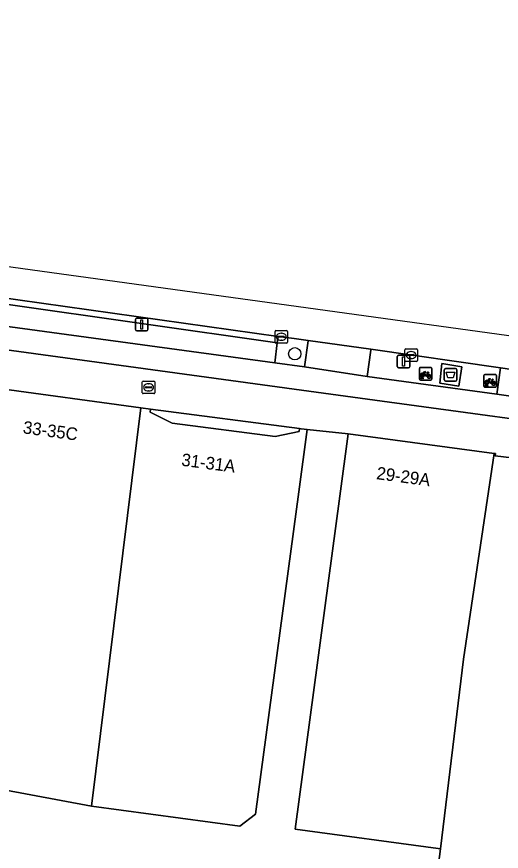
# Model space of a CAD drawing. Extents: x 160663 to 161506, y 382245 to 383291.
# Drawn here: x 160949.6 to 160988.3, y 383209.3 to 383275.8 of the extents above; entities that cross this region are included whole.
import ezdxf

# ---------------------------------------------------------------- set-up
doc = ezdxf.new("R2010")
doc.units = 0
for name, color, linetype in [('IMGEO_Afval_apart_plaats', 7, 'Continuous'), ('IMGEO_Berm_open', 7, 'Continuous'), ('IMGEO_Boom', 7, 'Continuous'), ('IMGEO_Brandkraan', 7, 'Continuous'), ('IMGEO_Erf', 7, 'Continuous'), ('IMGEO_Fietsenrek', 7, 'Continuous'), ('IMGEO_Fietspad_gesloten', 7, 'Continuous'), ('IMGEO_Groenvoorziening', 7, 'Continuous'), ('IMGEO_Kolk', 7, 'Continuous'), ('IMGEO_Lichtmast', 7, 'Continuous'), ('IMGEO_Pand', 7, 'Continuous'), ('IMGEO_Pand_nummerreeks', 7, 'Continuous'), ('IMGEO_Rijbaan_lokaal_gesloten', 7, 'Continuous'), ('IMGEO_Voetpad_gesloten', 7, 'Continuous'), ('IMGEO_Voetpad_open', 7, 'Continuous')]:
    doc.layers.add(name, color=color, linetype=linetype)

msp = doc.modelspace()

# ---------------------------------------------------------------- linework, layer by layer
at = {"layer": 'IMGEO_Afval_apart_plaats'}
for p, q in [((160983.737, 383246.899), (160983.737, 383247.699)), ((160983.737, 383247.699), (160983.737, 383246.899)), ((160983.837, 383247.799), (160984.627, 383247.799)), ((160984.627, 383247.799), (160983.837, 383247.799)), ((160984.727, 383247.699), (160984.727, 383246.899)), ((160984.727, 383246.899), (160984.727, 383247.699)), ((160984.627, 383246.799), (160983.837, 383246.799)), ((160983.837, 383246.799), (160984.627, 383246.799))]:
    msp.add_line(p, q, dxfattribs=at)
msp.add_lwpolyline([(160983.88, 383247.513), (160984.584, 383247.513), (160984.435, 383247.043), (160984.029, 383247.043), (160983.88, 383247.513)], dxfattribs=at)
for centre, start, end in [((160983.837, 383247.699), 90, 180), ((160983.837, 383247.699), 90, 180), ((160984.627, 383247.699), 0, 90), ((160984.627, 383247.699), 360, 90), ((160983.837, 383246.899), 180, 270), ((160983.837, 383246.899), 180, 270), ((160984.627, 383246.899), 270, 0), ((160984.627, 383246.899), 270, 0)]:
    msp.add_arc(centre, 0.1, start, end, dxfattribs=at)
at = {"layer": 'IMGEO_Berm_open'}
for points in [[(160948.754, 383252.914), (160948.513, 383251.198), (160970.219, 383248.244), (160970.397, 383249.839)], [(160988.207, 383247.841), (160977.884, 383249.337), (160977.874, 383249.265), (160977.584, 383247.17), (160987.927, 383245.742)], [(160983.544, 383248.211), (160985.124, 383247.921), (160984.884, 383246.395), (160983.384, 383246.637)]]:
    msp.add_lwpolyline(points, close=True, dxfattribs=at)
at = {"layer": 'IMGEO_Boom'}
msp.add_circle((160971.806, 383248.972), 0.489, dxfattribs=at)
at = {"layer": 'IMGEO_Brandkraan'}
for p, q in [((160959.648, 383245.873), (160959.648, 383246.725)), ((160959.723, 383246.799), (160960.575, 383246.799)), ((160959.907, 383246.293), (160959.907, 383246.305)), ((160960.345, 383246.256), (160959.947, 383246.256)), ((160959.95, 383246.342), (160960.348, 383246.342)), ((160960.136, 383246.579), (160960.161, 383246.579)), ((160960.391, 383246.305), (160960.391, 383246.293)), ((160960.649, 383246.725), (160960.649, 383245.873)), ((160960.575, 383245.799), (160959.723, 383245.799)), ((160960.159, 383246.019), (160960.134, 383246.019))]:
    msp.add_line(p, q, dxfattribs=at)
for points in [[(160959.648, 383245.873), (160959.648, 383246.725)], [(160959.723, 383246.799), (160960.575, 383246.799)], [(160960.649, 383246.725), (160960.649, 383245.873)], [(160960.575, 383245.799), (160959.723, 383245.799)]]:
    msp.add_lwpolyline(points, dxfattribs=at)
for centre, radius, start, end in [((160959.725, 383246.723), 0.0765, 91.55205, 178.44795), ((160959.725, 383246.723), 0.0765, 91.55205, 178.44795), ((160959.947, 383246.302), 0.0403, 85.87752, 175.75265), ((160959.944, 383246.292), 0.0366, 178.93798, 274.71019), ((160960.348, 383246.299), 0.043, 264.86636, 352.45326), ((160960.352, 383246.304), 0.0386, 1.73085, 96.63898), ((160960.573, 383246.723), 0.0765, 1.55205, 88.44795), ((160960.573, 383246.723), 0.0765, 1.55205, 88.44795), ((160959.725, 383245.875), 0.0765, 181.55205, 268.44795), ((160959.725, 383245.875), 0.0765, 181.55205, 268.44795), ((160960.573, 383245.875), 0.0765, 271.55205, 358.44795), ((160960.573, 383245.875), 0.0765, 271.55205, 358.44795)]:
    msp.add_arc(centre, radius, start, end, dxfattribs=at)
for centre, major_axis, ratio, start_param, end_param in [((160960.135, 383246.299), (-0.387, 0.002), 0.722429, 4.712389, 7.853982), ((160960.16, 383246.299), (-0.39, 0.002), 0.717154, 1.570796, 4.712389)]:
    msp.add_ellipse(centre, major_axis=major_axis, ratio=ratio, start_param=start_param, end_param=end_param, dxfattribs=at)
at = {"layer": 'IMGEO_Erf'}
msp.add_lwpolyline([(160982.349, 383201.177), (160983.434, 383209.525), (160983.247, 383209.55), (160971.844, 383211.082), (160975.411, 383237.636), (160976.076, 383242.591), (160972.798, 383242.937), (160972.132, 383237.982), (160968.68, 383212.278), (160967.425, 383211.32), (160955.6, 383212.908), (160943.461, 383215.168)], dxfattribs=at)
at = {"layer": 'IMGEO_Fietsenrek'}
for p, q in [((160981.749, 383246.957), (160981.749, 383247.798)), ((160981.749, 383247.798), (160981.749, 383246.957)), ((160981.824, 383247.882), (160982.665, 383247.882)), ((160982.665, 383247.882), (160981.824, 383247.882)), ((160982.749, 383247.807), (160982.749, 383246.966)), ((160982.749, 383246.966), (160982.749, 383247.807)), ((160982.674, 383246.882), (160981.833, 383246.882)), ((160981.833, 383246.882), (160982.674, 383246.882)), ((160981.876, 383246.966), (160981.915, 383247.126)), ((160981.91, 383246.966), (160981.876, 383246.966)), ((160981.945, 383247.114), (160981.91, 383246.966)), ((160981.987, 383247.138), (160981.986, 383247.142)), ((160982.028, 383246.966), (160981.994, 383247.108)), ((160982.018, 383247.149), (160982.019, 383247.142)), ((160982.026, 383247.112), (160982.061, 383246.966)), ((160982.061, 383246.966), (160982.028, 383246.966)), ((160982.436, 383247.431), (160982.472, 383247.336)), ((160986.888, 383246.39), (160986.888, 383247.231)), ((160986.888, 383247.231), (160986.888, 383246.39)), ((160986.963, 383247.315), (160987.804, 383247.315)), ((160987.804, 383247.315), (160986.963, 383247.315)), ((160987.575, 383246.864), (160987.611, 383246.769)), ((160987.888, 383247.24), (160987.888, 383246.399)), ((160987.888, 383246.399), (160987.888, 383247.24)), ((160987.813, 383246.315), (160986.972, 383246.315)), ((160986.972, 383246.315), (160987.813, 383246.315)), ((160987.015, 383246.399), (160987.054, 383246.559)), ((160987.049, 383246.399), (160987.015, 383246.399)), ((160987.084, 383246.547), (160987.049, 383246.399)), ((160987.126, 383246.571), (160987.125, 383246.575)), ((160987.167, 383246.399), (160987.133, 383246.541)), ((160987.157, 383246.582), (160987.158, 383246.575)), ((160987.165, 383246.545), (160987.2, 383246.399)), ((160987.2, 383246.399), (160987.167, 383246.399))]:
    msp.add_line(p, q, dxfattribs=at)
for points in [[(160982.062, 383247.408), (160982.157, 383247.572), (160982.243, 383247.558), (160982.245, 383247.549), (160982.189, 383247.538), (160982.162, 383247.493), (160982.418, 383247.452)], [(160982.083, 383247.356), (160982.031, 383247.266), (160981.991, 383247.241), (160981.992, 383247.288), (160982.047, 383247.382)], [(160982.358, 383247.164), (160982.308, 383247.164), (160982.117, 383247.415), (160982.098, 383247.383)], [(160982.405, 383247.427), (160982.148, 383247.468), (160982.131, 383247.439), (160982.298, 383247.219), (160982.405, 383247.427)], [(160982.453, 383247.329), (160982.423, 383247.406), (160982.314, 383247.188), (160982.357, 383247.188)], [(160982.387, 383247.188), (160982.507, 383247.187), (160982.463, 383247.301)], [(160982.483, 383247.308), (160982.538, 383247.163), (160982.388, 383247.163)], [(160982.418, 383247.452), (160982.443, 383247.501), (160982.437, 383247.505), (160982.414, 383247.509), (160982.402, 383247.516), (160982.401, 383247.519), (160982.403, 383247.524), (160982.498, 383247.509), (160982.5, 383247.499), (160982.49, 383247.486), (160982.478, 383247.48), (160982.464, 383247.486), (160982.436, 383247.431)], [(160987.201, 383246.841), (160987.296, 383247.005), (160987.382, 383246.991), (160987.384, 383246.982), (160987.328, 383246.971), (160987.301, 383246.926), (160987.557, 383246.885)], [(160987.544, 383246.86), (160987.287, 383246.901), (160987.27, 383246.872), (160987.437, 383246.652), (160987.544, 383246.86)], [(160987.557, 383246.885), (160987.582, 383246.934), (160987.576, 383246.938), (160987.553, 383246.942), (160987.541, 383246.949), (160987.54, 383246.952), (160987.542, 383246.957), (160987.637, 383246.942), (160987.639, 383246.932), (160987.629, 383246.919), (160987.617, 383246.913), (160987.603, 383246.919), (160987.575, 383246.864)], [(160987.222, 383246.789), (160987.17, 383246.699), (160987.13, 383246.674), (160987.131, 383246.721), (160987.186, 383246.815)], [(160987.497, 383246.597), (160987.447, 383246.597), (160987.256, 383246.848), (160987.237, 383246.816)], [(160987.592, 383246.762), (160987.562, 383246.839), (160987.453, 383246.621), (160987.496, 383246.621)], [(160987.526, 383246.621), (160987.646, 383246.62), (160987.602, 383246.734)], [(160987.622, 383246.741), (160987.677, 383246.596), (160987.527, 383246.596)]]:
    msp.add_lwpolyline(points, dxfattribs=at)
for centre, radius, start, end in [((160981.827, 383247.804), 0.0779, 92.4484, 184.28452), ((160981.827, 383247.804), 0.0779, 92.4484, 184.28452), ((160982.671, 383247.804), 0.0779, 2.4484, 94.28452), ((160982.671, 383247.804), 0.0779, 2.4484, 94.28452), ((160981.827, 383246.96), 0.0779, 182.4484, 274.28452), ((160981.827, 383246.96), 0.0779, 182.4484, 274.28452), ((160981.989, 383247.267), 0.159, 62.67661, 242.13685), ((160981.989, 383247.267), 0.129, 63.31916, 238.90302), ((160981.969, 383247.138), 0.0499, 12.8025, 158.69338), ((160981.989, 383247.267), 0.159, 253.99666, 271.78671), ((160981.969, 383247.138), 0.0174, 12.8025, 163.45023), ((160981.989, 383247.267), 0.129, 253.41502, 269.02044), ((160981.989, 383247.267), 0.129, 283.60429, 43.43025), ((160981.989, 383247.267), 0.159, 283.5766, 46.60424), ((160982.516, 383247.183), 0.159, 113.3408, 178.32165), ((160982.516, 383247.183), 0.159, 187.0065, 105.77075), ((160982.516, 383247.183), 0.129, 113.92302, 177.95563), ((160982.516, 383247.183), 0.129, 188.67146, 104.58832), ((160982.671, 383246.96), 0.0779, 272.4484, 4.28452), ((160982.671, 383246.96), 0.0779, 272.4484, 4.28452), ((160986.966, 383247.237), 0.0779, 92.4484, 184.28452), ((160986.966, 383247.237), 0.0779, 92.4484, 184.28452), ((160987.81, 383247.237), 0.0779, 2.4484, 94.28452), ((160987.81, 383247.237), 0.0779, 2.4484, 94.28452), ((160986.966, 383246.393), 0.0779, 182.4484, 274.28452), ((160986.966, 383246.393), 0.0779, 182.4484, 274.28452), ((160987.128, 383246.7), 0.159, 62.67661, 242.13685), ((160987.128, 383246.7), 0.129, 63.31916, 238.90302), ((160987.108, 383246.571), 0.0499, 12.8025, 158.69338), ((160987.128, 383246.7), 0.159, 253.99666, 271.78671), ((160987.108, 383246.571), 0.0174, 12.8025, 163.45023), ((160987.128, 383246.7), 0.129, 253.41502, 269.02044), ((160987.128, 383246.7), 0.129, 283.60429, 43.43025), ((160987.128, 383246.7), 0.159, 283.5766, 46.60424), ((160987.655, 383246.616), 0.159, 113.3408, 178.32165), ((160987.655, 383246.616), 0.159, 187.0065, 105.77075), ((160987.655, 383246.616), 0.129, 113.92302, 177.95563), ((160987.655, 383246.616), 0.129, 188.67146, 104.58832), ((160987.81, 383246.393), 0.0779, 272.4484, 4.28452), ((160987.81, 383246.393), 0.0779, 272.4484, 4.28452)]:
    msp.add_arc(centre, radius, start, end, dxfattribs=at)
at = {"layer": 'IMGEO_Fietspad_gesloten'}
for points in [[(160749.571, 383275.838), (160772.375, 383273.271), (160826.897, 383266.189), (160865.807, 383260.226), (160871.952, 383259.299), (160876.01, 383258.649), (160907.21, 383254.866), (160915.937, 383253.784), (160972.356, 383246.078), (160977.609, 383245.36), (160998.315, 383242.532), (161054.596, 383234.67)], [(161048.826, 383237.337), (161033.753, 383239.417), (161030.202, 383239.907), (161012.954, 383242.288), (161007.978, 383242.975), (160991.087, 383245.306), (160987.927, 383245.742), (160977.584, 383247.17), (160972.582, 383247.922), (160970.219, 383248.244), (160948.513, 383251.198), (160944.615, 383251.729), (160929.927, 383253.728), (160926.09, 383254.25), (160916.951, 383255.494), (160906.447, 383256.836), (160882.483, 383259.669), (160873.765, 383260.871), (160866.022, 383262.062), (160855.96, 383263.61), (160850.573, 383264.439)]]:
    msp.add_lwpolyline(points, dxfattribs=at)
at = {"layer": 'IMGEO_Groenvoorziening'}
for points in [[(160972.877, 383250.012), (160972.88, 383250.034), (160971.748, 383250.181), (160970.494, 383250.343), (160970.397, 383249.839), (160970.219, 383248.244), (160972.582, 383247.922)], [(160991.255, 383246.905), (160991.289, 383247.261), (160991.302, 383247.393), (160988.207, 383247.841), (160987.927, 383245.742), (160991.087, 383245.306)]]:
    msp.add_lwpolyline(points, close=True, dxfattribs=at)
at = {"layer": 'IMGEO_Kolk'}
for p, q in [((160970.232, 383249.901), (160970.232, 383250.753)), ((160970.307, 383250.827), (160971.159, 383250.827)), ((160970.491, 383250.321), (160970.491, 383250.333)), ((160970.929, 383250.284), (160970.531, 383250.284)), ((160970.534, 383250.37), (160970.932, 383250.37)), ((160970.72, 383250.607), (160970.745, 383250.607)), ((160970.975, 383250.333), (160970.975, 383250.321)), ((160971.233, 383250.753), (160971.233, 383249.901)), ((160971.159, 383249.827), (160970.307, 383249.827)), ((160970.743, 383250.047), (160970.718, 383250.047)), ((160980.584, 383248.441), (160980.584, 383249.293)), ((160980.659, 383249.367), (160981.511, 383249.367)), ((160980.843, 383248.861), (160980.843, 383248.873)), ((160980.886, 383248.91), (160981.284, 383248.91)), ((160981.072, 383249.147), (160981.097, 383249.147)), ((160981.327, 383248.873), (160981.327, 383248.861)), ((160981.585, 383249.293), (160981.585, 383248.441)), ((160981.511, 383248.367), (160980.659, 383248.367)), ((160981.281, 383248.824), (160980.883, 383248.824)), ((160981.095, 383248.587), (160981.07, 383248.587))]:
    msp.add_line(p, q, dxfattribs=at)
for points in [[(160970.232, 383249.901), (160970.232, 383250.753)], [(160970.307, 383250.827), (160971.159, 383250.827)], [(160971.233, 383250.753), (160971.233, 383249.901)], [(160971.159, 383249.827), (160970.307, 383249.827)], [(160980.584, 383248.441), (160980.584, 383249.293)], [(160980.659, 383249.367), (160981.511, 383249.367)], [(160981.585, 383249.293), (160981.585, 383248.441)], [(160981.511, 383248.367), (160980.659, 383248.367)]]:
    msp.add_lwpolyline(points, dxfattribs=at)
for centre, radius, start, end in [((160970.309, 383250.751), 0.0765, 91.55205, 178.44795), ((160970.309, 383250.751), 0.0765, 91.55205, 178.44795), ((160970.531, 383250.33), 0.0403, 85.87752, 175.75265), ((160970.528, 383250.32), 0.0366, 178.93798, 274.71019), ((160970.932, 383250.327), 0.043, 264.86636, 352.45326), ((160970.936, 383250.332), 0.0386, 1.73085, 96.63898), ((160971.157, 383250.751), 0.0765, 1.55205, 88.44795), ((160971.157, 383250.751), 0.0765, 1.55205, 88.44795), ((160970.309, 383249.903), 0.0765, 181.55205, 268.44795), ((160970.309, 383249.903), 0.0765, 181.55205, 268.44795), ((160971.157, 383249.903), 0.0765, 271.55205, 358.44795), ((160971.157, 383249.903), 0.0765, 271.55205, 358.44795), ((160980.661, 383249.291), 0.0765, 91.55205, 178.44795), ((160980.661, 383249.291), 0.0765, 91.55205, 178.44795), ((160980.883, 383248.87), 0.0403, 85.87752, 175.75265), ((160980.88, 383248.86), 0.0366, 178.93798, 274.71019), ((160981.284, 383248.867), 0.043, 264.86636, 352.45326), ((160981.288, 383248.872), 0.0386, 1.73085, 96.63898), ((160981.509, 383249.291), 0.0765, 1.55205, 88.44795), ((160981.509, 383249.291), 0.0765, 1.55205, 88.44795), ((160980.661, 383248.443), 0.0765, 181.55205, 268.44795), ((160980.661, 383248.443), 0.0765, 181.55205, 268.44795), ((160981.509, 383248.443), 0.0765, 271.55205, 358.44795), ((160981.509, 383248.443), 0.0765, 271.55205, 358.44795)]:
    msp.add_arc(centre, radius, start, end, dxfattribs=at)
for centre, major_axis, ratio, start_param, end_param in [((160970.719, 383250.327), (-0.387, 0.002), 0.722429, 4.712389, 7.853982), ((160970.744, 383250.327), (-0.39, 0.002), 0.717154, 1.570796, 4.712389), ((160981.071, 383248.867), (-0.387, 0.002), 0.722429, 4.712389, 7.853982), ((160981.096, 383248.867), (-0.39, 0.002), 0.717154, 1.570796, 4.712389)]:
    msp.add_ellipse(centre, major_axis=major_axis, ratio=ratio, start_param=start_param, end_param=end_param, dxfattribs=at)
at = {"layer": 'IMGEO_Lichtmast'}
for p, q in [((160959.103, 383250.904), (160959.103, 383251.704)), ((160959.103, 383251.704), (160959.103, 383250.904)), ((160959.203, 383251.804), (160959.993, 383251.804)), ((160959.993, 383251.804), (160959.203, 383251.804)), ((160960.093, 383251.704), (160960.093, 383250.904)), ((160960.093, 383250.904), (160960.093, 383251.704)), ((160959.993, 383250.804), (160959.203, 383250.804)), ((160959.203, 383250.804), (160959.993, 383250.804)), ((160979.987, 383247.955), (160979.987, 383248.755)), ((160979.987, 383248.755), (160979.987, 383247.955)), ((160980.087, 383248.855), (160980.877, 383248.855)), ((160980.877, 383248.855), (160980.087, 383248.855)), ((160980.977, 383248.755), (160980.977, 383247.955)), ((160980.977, 383247.955), (160980.977, 383248.755)), ((160980.877, 383247.855), (160980.087, 383247.855)), ((160980.087, 383247.855), (160980.877, 383247.855))]:
    msp.add_line(p, q, dxfattribs=at)
for points in [[(160959.523, 383251.679), (160959.673, 383251.679), (160959.673, 383250.929), (160959.523, 383250.929), (160959.523, 383251.679)], [(160980.407, 383248.73), (160980.557, 383248.73), (160980.557, 383247.98), (160980.407, 383247.98), (160980.407, 383248.73)]]:
    msp.add_lwpolyline(points, dxfattribs=at)
for centre, start, end in [((160959.203, 383251.704), 90, 180), ((160959.203, 383251.704), 90, 180), ((160959.993, 383251.704), 0, 90), ((160959.993, 383251.704), 360, 90), ((160959.203, 383250.904), 180, 270), ((160959.203, 383250.904), 180, 270), ((160959.993, 383250.904), 270, 0), ((160959.993, 383250.904), 270, 0), ((160980.087, 383248.755), 90, 180), ((160980.087, 383248.755), 90, 180), ((160980.877, 383248.755), 0, 90), ((160980.877, 383248.755), 360, 90), ((160980.087, 383247.955), 180, 270), ((160980.087, 383247.955), 180, 270), ((160980.877, 383247.955), 270, 0), ((160980.877, 383247.955), 270, 0)]:
    msp.add_arc(centre, 0.1, start, end, dxfattribs=at)
at = {"layer": 'IMGEO_Pand'}
for points in [[(160947.824, 383246.256), (160946.561, 383237.354), (160945.22, 383227.565), (160943.492, 383215.388), (160943.461, 383215.168), (160955.6, 383212.908), (160959.522, 383244.673)], [(160955.6, 383212.908), (160967.425, 383211.32), (160968.68, 383212.278), (160972.132, 383237.982), (160972.798, 383242.937), (160972.323, 383243.001), (160972.192, 383243.017), (160972.16, 383242.77), (160970.254, 383242.383), (160962.034, 383243.455), (160960.279, 383244.319), (160960.312, 383244.566), (160959.522, 383244.673)], [(160987.706, 383241.028), (160976.076, 383242.591), (160975.411, 383237.636), (160971.844, 383211.082), (160983.247, 383209.55), (160983.434, 383209.525), (160985.263, 383224.635)], [(160991.733, 383221.027), (160992.361, 383220.968), (160992.489, 383221.987), (160991.144, 383222.191), (160991.285, 383223.122), (160991.989, 383223.002), (160994.411, 383240.035), (160987.783, 383240.842), (160987.806, 383241.015), (160987.706, 383241.028), (160985.263, 383224.635), (160983.434, 383209.525), (160982.349, 383201.177), (160981.134, 383192.067), (160988.36, 383190.705), (160988.738, 383193.679)]]:
    msp.add_lwpolyline(points, close=True, dxfattribs=at)
at = {"layer": 'IMGEO_Rijbaan_lokaal_gesloten'}
msp.add_lwpolyline([(161038.265, 383243.607), (160926.374, 383259.023), (160926.118, 383256.999), (160926.07, 383256.622), (160926.395, 383256.579), (160930.26, 383256.062), (160941.434, 383254.466), (160944.887, 383253.96), (160947.814, 383253.531), (160970.494, 383250.343), (160971.748, 383250.181), (160972.88, 383250.034), (160977.884, 383249.337), (160988.207, 383247.841), (160991.302, 383247.393), (160999.446, 383246.282), (161008.184, 383245.068), (161013.209, 383244.37), (161020.794, 383243.317), (161030.482, 383241.923), (161034.004, 383241.447), (161038.92, 383240.782)], dxfattribs=at)
at = {"layer": 'IMGEO_Voetpad_gesloten'}
msp.add_lwpolyline([(160985.124, 383247.921), (160983.544, 383248.211), (160983.384, 383246.637), (160984.884, 383246.395)], close=True, dxfattribs=at)
at = {"layer": 'IMGEO_Voetpad_open'}
for points in [[(160998.315, 383242.532), (160977.609, 383245.36), (160972.356, 383246.078), (160915.937, 383253.784)], [(160947.824, 383246.256), (160959.522, 383244.673), (160960.312, 383244.566), (160972.192, 383243.017), (160972.323, 383243.001), (160972.798, 383242.937), (160976.076, 383242.591), (160987.706, 383241.028), (160987.806, 383241.015), (160987.783, 383240.842), (160994.411, 383240.035)]]:
    msp.add_lwpolyline(points, dxfattribs=at)
for points in [[(160970.494, 383250.343), (160947.814, 383253.531), (160948.754, 383252.914), (160970.397, 383249.839)], [(160977.874, 383249.265), (160977.884, 383249.337), (160972.88, 383250.034), (160972.877, 383250.012), (160972.582, 383247.922), (160977.584, 383247.17)], [(160972.192, 383243.017), (160960.312, 383244.566), (160960.279, 383244.319), (160962.034, 383243.455), (160970.254, 383242.383), (160972.16, 383242.77)]]:
    msp.add_lwpolyline(points, close=True, dxfattribs=at)

# ---------------------------------------------------------------- texts
at = {"layer": 'IMGEO_Pand_nummerreeks'}
for s, rotation, p in [('33-35C', 352.29222, (160950.08, 383242.641)), ('31-31A', 352.56978, (160962.722, 383240.057)), ('29-29A', 352.34528, (160978.276, 383238.986))]:
    msp.add_text(s, height=1, rotation=rotation, dxfattribs=at).set_placement(p)

doc.saveas('drawing.dxf')
